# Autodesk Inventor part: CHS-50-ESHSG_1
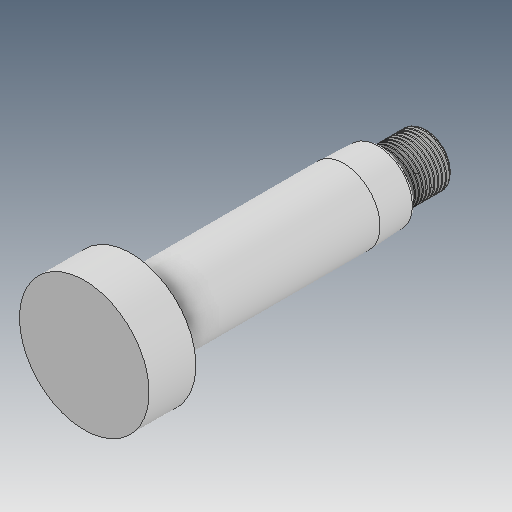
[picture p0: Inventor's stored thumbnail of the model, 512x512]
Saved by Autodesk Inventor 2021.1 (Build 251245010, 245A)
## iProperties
Created: 2019-04
Part Number: CHS-50-ESHSG_1
Material: Ogólny
Document SubType Name: Modeling
Designer: user
Density: 1 g/cm^3
Appearance: Domyślna
Author: user
Revision Number: ÈÎºÎ
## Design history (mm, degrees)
feature "ÊäÈë1"
node "Bryła1"
